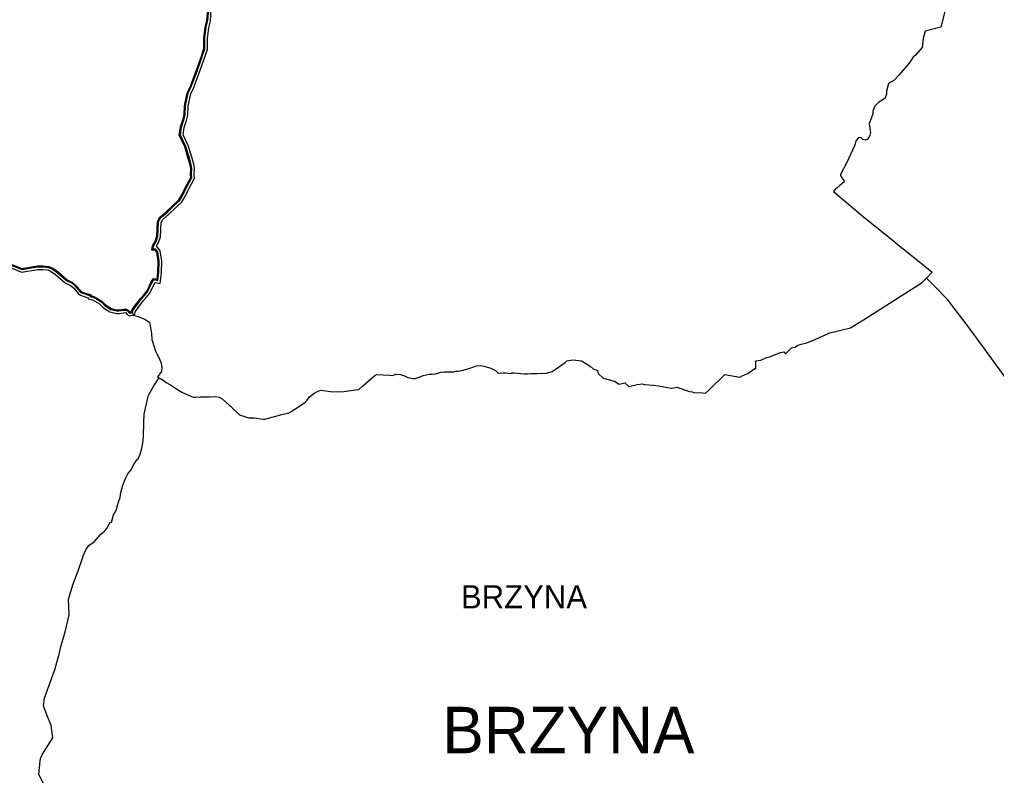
# Model space of a CAD drawing. Extents: x -562952 to -547638, y 190691 to 208158.
# Drawn here: x -556696 to -552912, y 196451 to 199380 of the extents above; entities that cross this region are included whole.
import ezdxf

# ---------------------------------------------------------------- set-up
doc = ezdxf.new("R2010")
doc.units = 0
for name, color, linetype in [('granica A_B', 7, 'Continuous'), ('granica_sołectwa', 7, 'Continuous'), ('nazwy miejscowości', 7, 'Continuous'), ('nazwy miejscowości DUŻE', 7, 'Continuous')]:
    doc.layers.add(name, color=color, linetype=linetype)

msp = doc.modelspace()

# ---------------------------------------------------------------- linework, layer by layer
at = {"layer": 'granica A_B'}
for points in [[(-556728.3, 198417.5), (-556688.4, 198401.3), (-556625.3, 198411.9), (-556605.7, 198411.9), (-556586.6, 198409.7), (-556573.2, 198404.1), (-556556.5, 198392.6), (-556519.1, 198360.3), (-556498.1, 198349.8), (-556485.8, 198339), (-556467.4, 198317.6), (-556459.8, 198311.6), (-556431, 198302.4), (-556428.4, 198298.4), (-556412.8, 198294.2), (-556395, 198284), (-556385.9, 198277.9), (-556371, 198263), (-556345.7, 198247), (-556319.4, 198240.8), (-556310.3, 198241.5), (-556285.3, 198244.8), (-556277, 198235.8), (-556269.5, 198231.6), (-556248.8, 198237.8), (-556248.2, 198248.1), (-556237.9, 198262.3), (-556215.3, 198291.6), (-556204.1, 198304.4), (-556191.4, 198319.5), (-556183, 198336.6), (-556170.7, 198361.2), (-556150.8, 198357.1), (-556146.4, 198398.9), (-556144.5, 198444.3), (-556150.6, 198484.1), (-556164.8, 198503.5), (-556157.5, 198515.6), (-556150.2, 198538.2), (-556147.6, 198593.4), (-556141.2, 198605.8), (-556118.9, 198624.1), (-556091.7, 198650.7), (-556068.5, 198670.7), (-556054.8, 198694.6), (-556041.5, 198721.5), (-556017.5, 198766), (-556019.9, 198780.8), (-556018.3, 198803.9), (-556021, 198819.1), (-556031.2, 198855.2), (-556043, 198891.6), (-556062.5, 198932.9), (-556058.2, 198961.1), (-556049.4, 198988.2), (-556044.5, 199009), (-556043.2, 199044), (-556032.5, 199091.5), (-556021.2, 199116.2), (-556000, 199172.9), (-555978.4, 199234), (-555967.9, 199264.9), (-555967.7, 199306.6), (-555962.7, 199348.1), (-555956.5, 199374.3), (-555953.2, 199420)], [(-556723.7, 198430.8), (-556686.8, 198415.7), (-556626.5, 198425.9), (-556604.9, 198425.9), (-556583.1, 198423.3), (-556566.5, 198416.5), (-556547.9, 198403.7), (-556511.2, 198372.1), (-556490.2, 198361.5), (-556475.8, 198348.9), (-556457.6, 198327.8), (-556453.1, 198324.1), (-556422, 198314.2), (-556419.6, 198310.5), (-556407.4, 198307.3), (-556387.7, 198295.9), (-556377, 198288.8), (-556362.2, 198274), (-556340.2, 198260), (-556318.3, 198254.9), (-556311.7, 198255.4), (-556293.1, 198257.9), (-556285.1, 198258.5), (-556275.3, 198254.6), (-556268.3, 198246.9), (-556267.9, 198246.7), (-556262.2, 198248.4), (-556262, 198251.4), (-556257.7, 198258.9), (-556249.1, 198270.7), (-556226.1, 198300.5), (-556214.7, 198313.6), (-556203.2, 198327.2), (-556195.6, 198342.8), (-556186.6, 198360.8), (-556177, 198376.9), (-556163.1, 198374), (-556160.4, 198399.9), (-556158.5, 198443.5), (-556164, 198478.6), (-556168.8, 198485.2), (-556171.6, 198486.7), (-556183.9, 198486.3), (-556180.7, 198502.6), (-556174.7, 198514.2), (-556170.3, 198521.4), (-556164.1, 198540.7), (-556161.4, 198597.1), (-556152.3, 198614.8), (-556128.3, 198634.5), (-556101.2, 198661), (-556079.5, 198679.7), (-556067.2, 198701.2), (-556054, 198727.9), (-556032.1, 198768.5), (-556034, 198780.2), (-556032.3, 198803.1), (-556034.6, 198815.9), (-556044.6, 198851.2), (-556056, 198886.5), (-556077, 198930.8), (-556071.9, 198964.3), (-556062.9, 198992), (-556058.5, 199010.9), (-556057.1, 199045.8), (-556045.9, 199096), (-556034.2, 199121.6), (-556013.2, 199177.7), (-555991.6, 199238.6), (-555981.9, 199267.3), (-555981.7, 199307.5), (-555976.5, 199350.6), (-555970.3, 199376.4), (-555967.1, 199421.4)]]:
    msp.add_lwpolyline(points, dxfattribs=at)
at = {"layer": 'granica_sołectwa'}
msp.add_line((-556161.4, 197995.4), (-556155.4, 197991.5), dxfattribs=at)
for points in [[(-556311.3, 198251.4), (-556292.7, 198253.9), (-556285.7, 198254.4), (-556277.6, 198251.2), (-556270.8, 198243.8), (-556268.3, 198242.4), (-556258.3, 198245.4), (-556258.1, 198250.2), (-556254.3, 198256.7), (-556245.9, 198268.3), (-556223, 198298), (-556211.7, 198311), (-556199.8, 198325), (-556192, 198341.1), (-556183.1, 198358.9), (-556175, 198372.4), (-556159.6, 198369.1), (-556156.4, 198399.6), (-556154.5, 198443.8), (-556160.2, 198480.2), (-556166.1, 198488.3), (-556170.7, 198490.7), (-556179, 198490.5), (-556176.9, 198501.2), (-556171.2, 198512.2), (-556166.6, 198519.8), (-556160.2, 198540), (-556157.5, 198596.1), (-556149.2, 198612.2), (-556125.6, 198631.5), (-556098.5, 198658.1), (-556076.3, 198677.2), (-556063.7, 198699.3), (-556050.4, 198726.1), (-556027.9, 198767.8), (-556029.9, 198780.4), (-556028.3, 198803.3), (-556030.7, 198816.8), (-556040.7, 198852.3), (-556052.3, 198888), (-556072.8, 198931.4), (-556068, 198963.4), (-556059.1, 198990.9), (-556054.5, 199010.3), (-556053.1, 199045.3), (-556042.1, 199094.7), (-556030.5, 199120), (-556009.4, 199176.3), (-555987.8, 199237.3), (-555977.9, 199266.6), (-555977.7, 199307.3), (-555972.6, 199349.9), (-555966.4, 199375.8), (-555963.1, 199421)], [(-553112.6, 199411.3), (-553127.4, 199350.8), (-553188.8, 199335), (-553196.3, 199306.5), (-553199.4, 199272.1), (-553226.3, 199242), (-553234.2, 199233.6), (-553250.1, 199211.4), (-553274.7, 199183.1), (-553290.7, 199164.1), (-553309.3, 199144.4), (-553329.9, 199131.8), (-553338.6, 199102.7), (-553337.6, 199091.4), (-553344.8, 199074.6), (-553367.3, 199060.1), (-553382.9, 199044.1), (-553391.5, 199024.9), (-553390.3, 199015), (-553403, 198983.4), (-553405.4, 198977.3), (-553401.5, 198950.5), (-553400.4, 198942.6), (-553402.4, 198931.9), (-553408.7, 198918), (-553418.6, 198913.1), (-553429.7, 198915.5), (-553438, 198922.6), (-553446.6, 198922), (-553455.9, 198911.5), (-553461.5, 198890.3), (-553491.3, 198826.5), (-553516, 198779.5), (-553516, 198777.2), (-553513.8, 198770.9), (-553501.1, 198752.4), (-553518.1, 198737.5), (-553530.8, 198726.5), (-553535.3, 198723.1), (-553543.6, 198713.3), (-553477.9, 198657.9), (-553434.7, 198622.6), (-553350.2, 198553.5), (-553280.3, 198497), (-553210.4, 198440.8), (-553160.8, 198401.1), (-553182.8, 198378.3)], [(-556725, 198427), (-556687.3, 198411.6), (-556626.2, 198421.9), (-556605.1, 198421.9), (-556584.1, 198419.4), (-556568.4, 198413), (-556550.4, 198400.5), (-556513.5, 198368.7), (-556492.4, 198358.2), (-556478.7, 198346.1), (-556460.4, 198324.9), (-556455, 198320.5), (-556424.6, 198310.8), (-556422.1, 198307), (-556408.9, 198303.5), (-556389.8, 198292.5), (-556379.5, 198285.7), (-556364.7, 198270.9), (-556341.7, 198256.3), (-556318.6, 198250.9), (-556311.3, 198251.4)], [(-553426.5, 198216.5), (-553360, 198259.1), (-553295.4, 198300.1), (-553199.5, 198361.4), (-553182.8, 198378.3)], [(-552283.3, 197326.8), (-552319.9, 197346.3), (-552347.6, 197357.8), (-552398.6, 197378.8), (-552444.7, 197398.1), (-552476, 197409.7), (-552500.2, 197428.9), (-552534.5, 197465.1), (-552592.6, 197516.5), (-552622.6, 197573.5), (-552698.5, 197710.1), (-552726.3, 197763.8), (-552794.1, 197862.8), (-552874.4, 197988.5), (-552888.5, 198008.4), (-552960.4, 198108.6), (-553029.7, 198200.8), (-553085, 198272.8), (-553100, 198294.1), (-553156.5, 198351), (-553182.8, 198378.3)], [(-556258.3, 198245.4), (-556255.5, 198234.3), (-556237.1, 198229), (-556217.3, 198221.4), (-556208.9, 198218.1), (-556192.1, 198206.9), (-556187.9, 198186.8), (-556184.6, 198163.6), (-556183.2, 198139.7), (-556171.2, 198103.6), (-556170.9, 198097.2), (-556159.2, 198075.4), (-556148.6, 198052.8), (-556144.7, 198035), (-556145.5, 198015.8), (-556161.4, 197995.4)], [(-554616.9, 198027.1), (-554595.2, 198041.7), (-554581.9, 198051.1), (-554575.6, 198057.5), (-554552.6, 198061.6), (-554519.8, 198057.7), (-554485.3, 198037), (-554474.5, 198027), (-554457.8, 198019.9), (-554455.2, 198008.1), (-554435.2, 197990.8), (-554391.1, 197979.4), (-554372.9, 197966.7), (-554351.2, 197971.9), (-554335.4, 197958.7), (-554303.8, 197966.1), (-554284.7, 197968.5), (-554275.1, 197966.3), (-554240.7, 197963.7), (-554221.6, 197961.1), (-554186.6, 197953.8), (-554169.3, 197952.2), (-554149, 197955.7), (-554124.4, 197947.2), (-554100.7, 197938.4), (-554091.2, 197937.6), (-554084.2, 197935.3), (-554048.8, 197933.2), (-554038.6, 197931.8), (-554027.6, 197942.3), (-553964.2, 198004.9), (-553906.5, 197994.8), (-553893.8, 198000.3), (-553874.8, 198008.9), (-553847.7, 198028.3), (-553843.6, 198028.1), (-553844.1, 198057.4), (-553824.4, 198059.8), (-553802.6, 198070.6), (-553789.7, 198073.6), (-553772, 198081.4), (-553748.3, 198090.6), (-553736.2, 198093), (-553729.2, 198084.5), (-553705.9, 198107.4), (-553692.3, 198110.9), (-553683.8, 198116.7), (-553668.5, 198122.1), (-553647.1, 198128), (-553611.1, 198142.2), (-553558.1, 198166.2), (-553477.2, 198184.9), (-553426.5, 198216.5)], [(-555381.9, 197946.3), (-555367.1, 197959.5), (-555336.1, 197986.5), (-555318.2, 198002.4), (-555311.9, 198004.8), (-555263, 198002.3), (-555250.4, 198001.2), (-555238.9, 198006), (-555220.9, 198004.3), (-555205.3, 197999.4), (-555191.4, 197993.1), (-555172.2, 197989.1), (-555163.8, 197989.4), (-555148.6, 197994.9), (-555133.1, 198001.4), (-555108.7, 198006.5), (-555097, 198006), (-555085.4, 198007.9), (-555063.1, 198013.6), (-555049.4, 198015.5), (-555024.2, 198014.7), (-555016, 198014.8), (-555013.5, 198015.3), (-555007, 198017.1), (-554996.9, 198018.2), (-554977.5, 198022), (-554955.7, 198028.2), (-554940.7, 198033.2), (-554927.5, 198037.8), (-554911.1, 198040), (-554897.6, 198037.6), (-554870.2, 198029.2), (-554852.7, 198020.1), (-554841.4, 198009.4), (-554839.3, 198009.7), (-554822.8, 198010.7), (-554813, 198010.8), (-554792.7, 198009.1), (-554791.2, 198009), (-554788.9, 198011.1), (-554779.5, 198011.6), (-554766.6, 198009.7), (-554756, 198008.1), (-554739.5, 198007.4), (-554728.6, 198007.3), (-554713.5, 198009.2), (-554690, 198008.9), (-554654.9, 198010.1), (-554633.1, 198016.4), (-554616.9, 198027.1)], [(-556583.2, 196382.2), (-556620.9, 196454.9), (-556617.4, 196495.1), (-556614.6, 196516.9), (-556606.9, 196534), (-556593.9, 196554.8), (-556567.2, 196597.6), (-556572.9, 196644.3), (-556589.6, 196686.4), (-556603.3, 196721.2), (-556598.8, 196750.6), (-556571.3, 196828.9), (-556564.3, 196848), (-556559.8, 196857), (-556542.6, 196921), (-556535.2, 196950.3), (-556530.1, 196967.6), (-556519.3, 197008), (-556503.5, 197074), (-556506.1, 197134.8), (-556488, 197194.1), (-556469.2, 197243.7), (-556452.4, 197293), (-556449.4, 197302.7), (-556439.5, 197325.3), (-556427.2, 197342.4), (-556404.9, 197357.7), (-556382.2, 197384.3), (-556367.3, 197398.1), (-556357.9, 197408), (-556344.5, 197432), (-556339.9, 197431.1), (-556331.8, 197460.7), (-556325.4, 197471.2), (-556320.5, 197482.6), (-556316.8, 197497.6), (-556312.6, 197509.9), (-556305.8, 197527.9), (-556303.7, 197547.7), (-556296.1, 197575.8), (-556285.3, 197601.4), (-556276.1, 197619.9), (-556264.1, 197634), (-556252.9, 197656.2), (-556241.2, 197673.5), (-556236.6, 197677.5), (-556228.1, 197696.5), (-556222.4, 197718.8), (-556217.9, 197738.2), (-556215.7, 197766.3), (-556213.9, 197818.5), (-556213, 197851.4), (-556198.9, 197914.5), (-556196.6, 197924.5), (-556176.2, 197960.3), (-556155.4, 197991.5)], [(-556155.4, 197991.5), (-556139.7, 197983), (-556127.4, 197973.1), (-556111.2, 197965.2), (-556087.3, 197949), (-556064.7, 197934.4), (-556023.4, 197917), (-556014.2, 197916.3), (-555994.6, 197917.7), (-555960.4, 197918.5), (-555936.6, 197919.8), (-555923.2, 197916.7), (-555911.5, 197910.9), (-555884, 197885.3), (-555878.7, 197881.9), (-555845.5, 197849.9), (-555843.5, 197848), (-555809.5, 197836.4), (-555786.5, 197836.4), (-555751.7, 197832.2), (-555745.1, 197832.3), (-555716.9, 197838.9), (-555680.4, 197849.3), (-555652.7, 197855.8), (-555643.4, 197861.1), (-555615.8, 197879.2), (-555589.2, 197897), (-555582.3, 197905.4), (-555573.2, 197917.8), (-555555.7, 197930.8), (-555547.8, 197935.9), (-555542.2, 197938.9), (-555537, 197941.5), (-555528, 197943.4), (-555491.8, 197938.5), (-555466.4, 197937.6), (-555439.2, 197939.1), (-555403.7, 197943.8), (-555383.3, 197946.5), (-555381.9, 197946.3)]]:
    msp.add_lwpolyline(points, dxfattribs=at)

# ---------------------------------------------------------------- texts
at = {"layer": 'nazwy miejscowości'}
msp.add_text('BRZYNA', height=90, dxfattribs=at).set_placement((-554986.1, 197098.5))
at = {"layer": 'nazwy miejscowości DUŻE'}
msp.add_text('BRZYNA', height=180, dxfattribs=at).set_placement((-555058, 196537.2))

doc.saveas('drawing.dxf')
